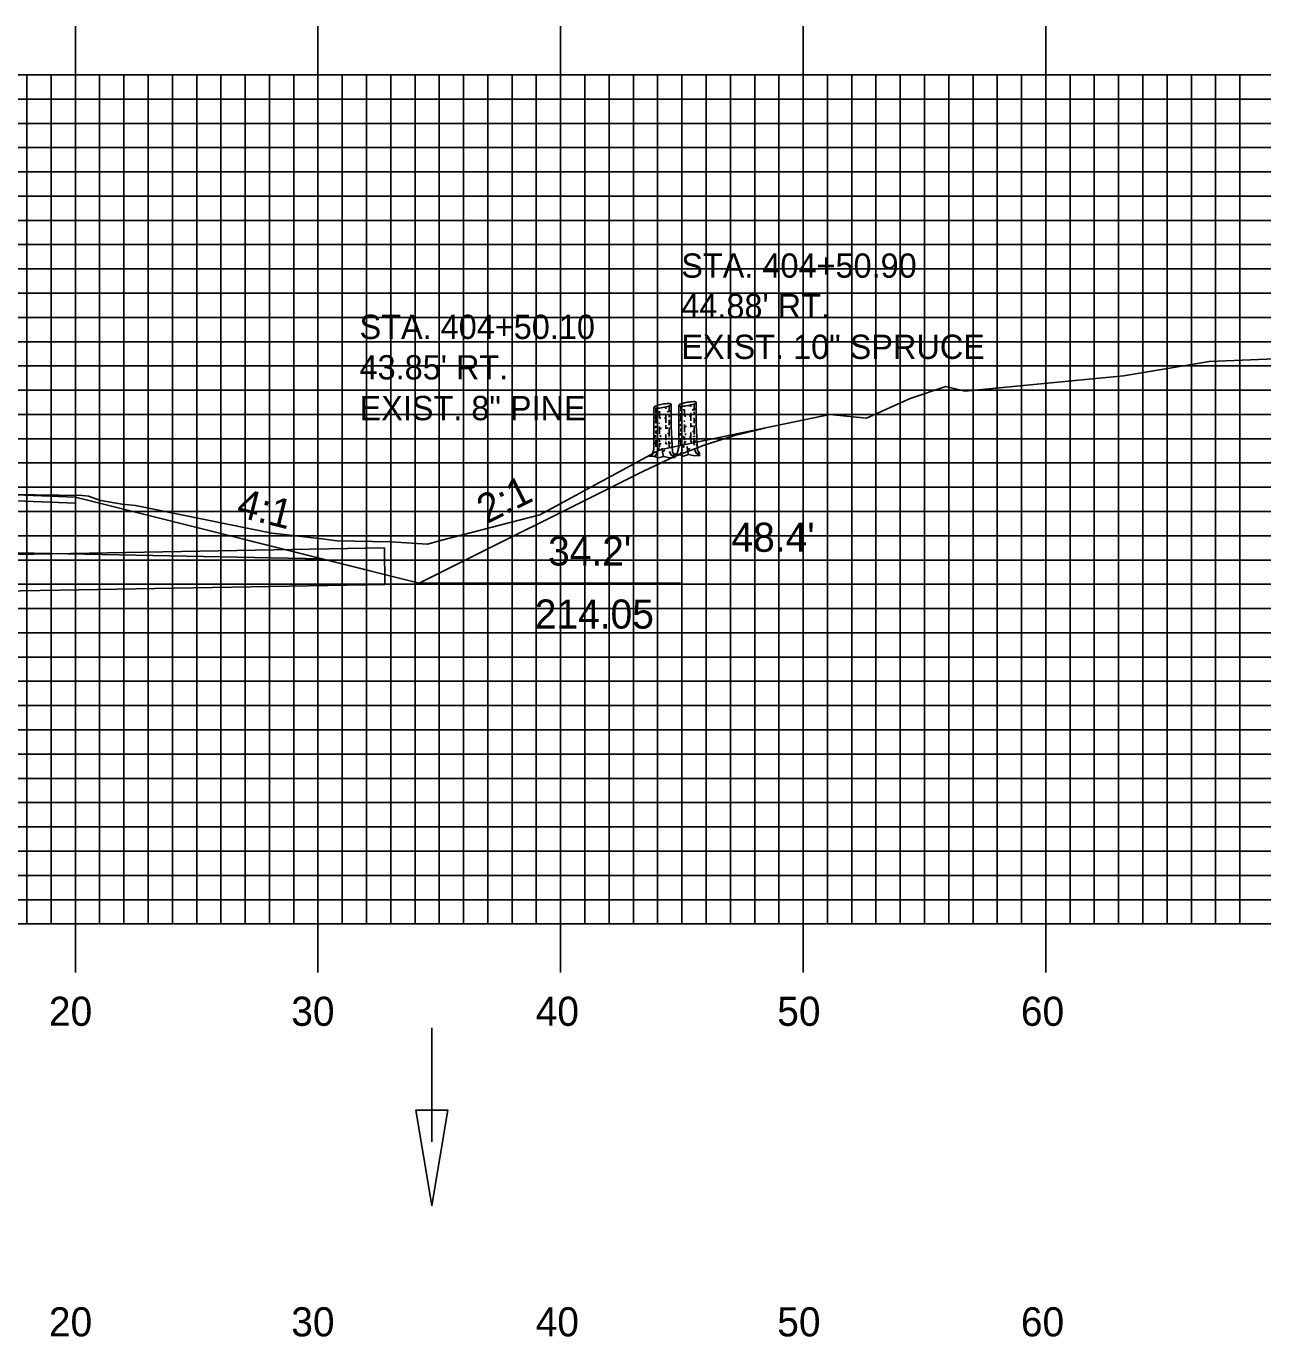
# Model space of a CAD drawing. Extents: x 851348 to 851692, y 364785 to 365005.
# Drawn here: x 851532.2 to 851583.1, y 364841.2 to 364895.2 of the extents above; entities that cross this region are included whole.
import ezdxf

# ---------------------------------------------------------------- set-up
doc = ezdxf.new("R2010")
doc.units = 0
for name, color, linetype in [('ANNOTATION', 7, 'Continuous'), ('D_Drainage_Culvert', 7, 'Continuous'), ('D_Drainage_Ditch_Line', 7, 'Continuous'), ('D_Roadway_Centerline', 7, 'Continuous'), ('D_Roadway_Edge_Shoulder', 7, 'Continuous'), ('D_Roadway_SlopeLines', 7, 'Continuous'), ('D_Roadway_SubGrade', 7, 'Continuous'), ('D_Text_Monospaced', 7, 'Continuous'), ('D_Text_Standard', 7, 'Continuous'), ('H_V ANNOTATION', 7, 'Continuous'), ('MAJOR', 7, 'Continuous'), ('MINOR', 7, 'Continuous'), ('PDRAIN', 7, 'Continuous'), ('S_Roadway_Centerline', 7, 'Continuous'), ('S_Trees_Conifer_NonPay', 7, 'Continuous')]:
    doc.layers.add(name, color=color, linetype=linetype)

msp = doc.modelspace()

# ---------------------------------------------------------------- linework, layer by layer
at = {"layer": 'D_Drainage_Culvert'}
msp.add_line((851472.732, 364872.438), (851546.926, 364873.729), dxfattribs=at)
msp.add_lwpolyline([(851472.732, 364872.438), (851472.758, 364870.938), (851546.952, 364872.229), (851546.926, 364873.729)], dxfattribs=at)
at = {"layer": 'D_Drainage_Ditch_Line'}
msp.add_line((851548.885, 364849.246), (851548.885, 364853.945), dxfattribs=at)
msp.add_lwpolyline([(851548.229, 364850.558), (851549.541, 364850.558), (851548.885, 364846.621)], close=True, dxfattribs=at)
at = {"layer": 'D_Roadway_Centerline'}
msp.add_lwpolyline([(851484.018, 364873.28), (851494.191, 364875.823), (851502.191, 364876.143), (851514.191, 364876.383), (851526.191, 364876.143), (851534.191, 364875.823), (851544.365, 364873.28), (851548.365, 364872.28), (851557.607, 364876.901), (851558.857, 364877.48), (851560.107, 364877.969), (851561.357, 364878.366), (851562.607, 364878.671)], dxfattribs=at)
at = {"layer": 'D_Roadway_Edge_Shoulder'}
msp.add_lwpolyline([(851526.191, 364876.143), (851534.191, 364875.823), (851534.191, 364875.573), (851526.191, 364875.893)], close=True, dxfattribs=at)
at = {"layer": 'D_Roadway_SlopeLines'}
for points in [[(851548.365, 364872.28), (851557.607, 364876.901), (851558.857, 364877.48), (851560.107, 364877.969), (851561.357, 364878.366), (851562.607, 364878.671)], [(851534.191, 364875.823), (851548.365, 364872.28)]]:
    msp.add_lwpolyline(points, dxfattribs=at)
at = {"layer": 'D_Roadway_SubGrade'}
msp.add_lwpolyline([(851502.191, 364873.643), (851484.018, 364873.28), (851494.191, 364875.823), (851494.191, 364875.573), (851502.191, 364875.893), (851514.191, 364876.133), (851526.191, 364875.893), (851534.191, 364875.573), (851534.191, 364875.823), (851544.365, 364873.28), (851526.191, 364873.643), (851514.191, 364873.883)], close=True, dxfattribs=at)
at = {"layer": 'MAJOR'}
for p, q in [((851534.191, 364895.237), (851534.191, 364893.233)), ((851544.191, 364895.237), (851544.191, 364893.233)), ((851554.191, 364895.237), (851554.191, 364893.233)), ((851564.191, 364895.237), (851564.191, 364893.233)), ((851574.191, 364895.237), (851574.191, 364893.233)), ((851374.191, 364893.233), (851654.191, 364893.233)), ((851374.191, 364893.233), (851654.191, 364893.233)), ((851534.191, 364858.233), (851534.191, 364893.233)), ((851544.191, 364858.233), (851544.191, 364893.233)), ((851554.191, 364858.233), (851554.191, 364893.233)), ((851564.191, 364858.233), (851564.191, 364893.233)), ((851574.191, 364858.233), (851574.191, 364893.233)), ((851374.191, 364888.233), (851654.191, 364888.233)), ((851374.191, 364883.233), (851654.191, 364883.233)), ((851374.191, 364878.233), (851654.191, 364878.233)), ((851374.191, 364873.233), (851654.191, 364873.233)), ((851374.191, 364868.233), (851654.191, 364868.233)), ((851374.191, 364863.233), (851654.191, 364863.233)), ((851374.191, 364858.233), (851654.191, 364858.233)), ((851374.191, 364858.233), (851654.191, 364858.233)), ((851534.191, 364856.229), (851534.191, 364858.233)), ((851544.191, 364856.229), (851544.191, 364858.233)), ((851554.191, 364856.229), (851554.191, 364858.233)), ((851564.191, 364856.229), (851564.191, 364858.233)), ((851574.191, 364856.229), (851574.191, 364858.233))]:
    msp.add_line(p, q, dxfattribs=at)
at = {"layer": 'MINOR'}
for p, q in [((851532.191, 364858.233), (851532.191, 364893.233)), ((851533.191, 364858.233), (851533.191, 364893.233)), ((851535.191, 364858.233), (851535.191, 364893.233)), ((851536.191, 364858.233), (851536.191, 364893.233)), ((851537.191, 364858.233), (851537.191, 364893.233)), ((851538.191, 364858.233), (851538.191, 364893.233)), ((851539.191, 364858.233), (851539.191, 364893.233)), ((851540.191, 364858.233), (851540.191, 364893.233)), ((851541.191, 364858.233), (851541.191, 364893.233)), ((851542.191, 364858.233), (851542.191, 364893.233)), ((851543.191, 364858.233), (851543.191, 364893.233)), ((851545.191, 364858.233), (851545.191, 364893.233)), ((851546.191, 364858.233), (851546.191, 364893.233)), ((851547.191, 364858.233), (851547.191, 364893.233)), ((851548.191, 364858.233), (851548.191, 364893.233)), ((851549.191, 364858.233), (851549.191, 364893.233)), ((851550.191, 364858.233), (851550.191, 364893.233)), ((851551.191, 364858.233), (851551.191, 364893.233)), ((851552.191, 364858.233), (851552.191, 364893.233)), ((851553.191, 364858.233), (851553.191, 364893.233)), ((851555.191, 364858.233), (851555.191, 364893.233)), ((851556.191, 364858.233), (851556.191, 364893.233)), ((851557.191, 364858.233), (851557.191, 364893.233)), ((851558.191, 364858.233), (851558.191, 364893.233)), ((851559.191, 364858.233), (851559.191, 364893.233)), ((851560.191, 364858.233), (851560.191, 364893.233)), ((851561.191, 364858.233), (851561.191, 364893.233)), ((851562.191, 364858.233), (851562.191, 364893.233)), ((851563.191, 364858.233), (851563.191, 364893.233)), ((851565.191, 364858.233), (851565.191, 364893.233)), ((851566.191, 364858.233), (851566.191, 364893.233)), ((851567.191, 364858.233), (851567.191, 364893.233)), ((851568.191, 364858.233), (851568.191, 364893.233)), ((851569.191, 364858.233), (851569.191, 364893.233)), ((851570.191, 364858.233), (851570.191, 364893.233)), ((851571.191, 364858.233), (851571.191, 364893.233)), ((851572.191, 364858.233), (851572.191, 364893.233)), ((851573.191, 364858.233), (851573.191, 364893.233)), ((851575.191, 364858.233), (851575.191, 364893.233)), ((851576.191, 364858.233), (851576.191, 364893.233)), ((851577.191, 364858.233), (851577.191, 364893.233)), ((851578.191, 364858.233), (851578.191, 364893.233)), ((851579.191, 364858.233), (851579.191, 364893.233)), ((851580.191, 364858.233), (851580.191, 364893.233)), ((851581.191, 364858.233), (851581.191, 364893.233)), ((851582.191, 364858.233), (851582.191, 364893.233)), ((851374.191, 364892.233), (851654.191, 364892.233)), ((851374.191, 364891.233), (851654.191, 364891.233)), ((851374.191, 364890.233), (851654.191, 364890.233)), ((851374.191, 364889.233), (851654.191, 364889.233)), ((851374.191, 364887.233), (851654.191, 364887.233)), ((851374.191, 364886.233), (851654.191, 364886.233)), ((851374.191, 364885.233), (851654.191, 364885.233)), ((851374.191, 364884.233), (851654.191, 364884.233)), ((851374.191, 364882.233), (851654.191, 364882.233)), ((851374.191, 364881.233), (851654.191, 364881.233)), ((851374.191, 364880.233), (851654.191, 364880.233)), ((851374.191, 364879.233), (851654.191, 364879.233)), ((851374.191, 364877.233), (851654.191, 364877.233)), ((851374.191, 364876.233), (851654.191, 364876.233)), ((851374.191, 364875.233), (851654.191, 364875.233)), ((851374.191, 364874.233), (851654.191, 364874.233)), ((851374.191, 364872.233), (851654.191, 364872.233)), ((851374.191, 364871.233), (851654.191, 364871.233)), ((851374.191, 364870.233), (851654.191, 364870.233)), ((851374.191, 364869.233), (851654.191, 364869.233)), ((851374.191, 364867.233), (851654.191, 364867.233)), ((851374.191, 364866.233), (851654.191, 364866.233)), ((851374.191, 364865.233), (851654.191, 364865.233)), ((851374.191, 364864.233), (851654.191, 364864.233)), ((851374.191, 364862.233), (851654.191, 364862.233)), ((851374.191, 364861.233), (851654.191, 364861.233)), ((851374.191, 364860.233), (851654.191, 364860.233)), ((851374.191, 364859.233), (851654.191, 364859.233))]:
    msp.add_line(p, q, dxfattribs=at)
at = {"layer": 'PDRAIN'}
msp.add_line((851548.365, 364872.28), (851559.136, 364872.28), dxfattribs=at)
at = {"layer": 'S_Roadway_Centerline'}
msp.add_lwpolyline([(851530.584, 364875.954), (851534.474, 364875.898), (851534.731, 364875.863), (851535.225, 364875.692), (851536.116, 364875.529), (851536.67, 364875.476), (851542.288, 364874.334), (851544.359, 364874.112), (851544.968, 364874.02), (851547.184, 364873.987), (851548.701, 364873.888), (851549.301, 364874.056), (851553.335, 364875.102), (851557.74, 364877.491), (851558.095, 364877.681), (851558.341, 364877.783), (851565.291, 364879.23), (851566.803, 364879.082), (851568.595, 364879.89), (851570.066, 364880.38), (851570.855, 364880.187), (851577.397, 364880.822), (851580.934, 364881.423), (851587.352, 364881.676)], dxfattribs=at)
at = {"layer": 'S_Trees_Conifer_NonPay'}
for p, q in [((851558.115, 364879.488), (851558.115, 364879.283)), ((851558.115, 364879.21), (851558.115, 364878.878)), ((851558.272, 364879.363), (851558.272, 364879.09)), ((851558.534, 364879.543), (851558.534, 364879.464)), ((851558.534, 364879.215), (851558.534, 364878.89)), ((851558.669, 364879.254), (851558.669, 364879.124)), ((851559.147, 364879.568), (851559.147, 364879.363)), ((851559.147, 364879.29), (851559.147, 364878.959)), ((851559.304, 364879.444), (851559.304, 364879.17)), ((851559.566, 364879.623), (851559.566, 364879.545)), ((851559.566, 364879.295), (851559.566, 364878.97)), ((851559.7, 364879.335), (851559.7, 364879.204)), ((851558.115, 364878.764), (851558.115, 364878.686)), ((851558.272, 364878.736), (851558.272, 364878.418)), ((851558.534, 364878.789), (851558.534, 364878.635)), ((851558.669, 364879.015), (851558.669, 364878.789)), ((851558.669, 364878.697), (851558.669, 364878.321)), ((851559.147, 364878.844), (851559.147, 364878.766)), ((851559.147, 364878.652), (851559.147, 364878.542)), ((851559.304, 364878.816), (851559.304, 364878.498)), ((851559.566, 364878.869), (851559.566, 364878.715)), ((851559.7, 364879.095), (851559.7, 364878.869)), ((851559.7, 364878.777), (851559.7, 364878.401)), ((851558.098, 364878.384), (851558.098, 364878.287)), ((851558.115, 364878.571), (851558.115, 364878.462)), ((851558.115, 364878.173), (851558.115, 364877.905)), ((851558.272, 364878.248), (851558.272, 364878.088)), ((851558.314, 364878.373), (851558.314, 364878.304)), ((851558.534, 364878.407), (851558.534, 364878.173)), ((851558.534, 364878.111), (851558.534, 364878.025)), ((851558.65, 364878.128), (851558.667, 364877.882)), ((851559.13, 364878.465), (851559.13, 364878.367)), ((851559.147, 364878.253), (851559.147, 364877.986)), ((851559.304, 364878.328), (851559.304, 364878.169)), ((851559.304, 364878.111), (851559.304, 364877.98)), ((851559.345, 364878.453), (851559.345, 364878.384)), ((851559.566, 364878.487), (851559.566, 364878.253)), ((851559.566, 364878.191), (851559.566, 364878.105)), ((851559.682, 364878.208), (851559.699, 364877.963)), ((851558.272, 364878.031), (851558.272, 364877.899)), ((851558.729, 364877.899), (851558.789, 364877.906)), ((851559.76, 364877.98), (851559.821, 364877.986))]:
    msp.add_line(p, q, dxfattribs=at)
for points in [[(851559.811, 364877.619), (851559.927, 364877.628), (851559.835, 364877.753), (851559.802, 364878.294), (851559.781, 364878.811), (851559.781, 364879.73)], [(851558.037, 364879.522), (851558.037, 364877.804), (851557.967, 364877.548), (851557.848, 364877.514), (851558.064, 364877.497), (851558.224, 364877.439), (851558.433, 364877.497), (851558.695, 364877.45), (851558.901, 364877.456), (851558.75, 364877.559), (851558.678, 364877.712)], [(851558.669, 364879.584), (851558.669, 364879.487), (851558.669, 364879.322)], [(851558.779, 364877.539), (851558.896, 364877.548), (851558.804, 364877.673), (851558.77, 364878.214), (851558.75, 364878.731), (851558.75, 364879.65)], [(851559.068, 364879.602), (851559.068, 364877.884), (851558.999, 364877.628), (851558.879, 364877.594), (851559.096, 364877.577), (851559.255, 364877.519), (851559.465, 364877.577), (851559.727, 364877.53), (851559.933, 364877.536), (851559.781, 364877.639), (851559.71, 364877.793)], [(851559.7, 364879.664), (851559.7, 364879.567), (851559.7, 364879.402)], [(851558.064, 364877.497), (851558.154, 364877.609), (851558.171, 364877.724)], [(851558.195, 364877.86), (851558.184, 364877.815), (851558.235, 364877.804), (851558.235, 364877.866)], [(851558.433, 364877.497), (851558.388, 364877.673), (851558.382, 364877.838)], [(851558.386, 364877.723), (851558.456, 364877.718), (851558.474, 364877.77)], [(851559.096, 364877.577), (851559.186, 364877.69), (851559.203, 364877.804)], [(851559.227, 364877.94), (851559.216, 364877.896), (851559.266, 364877.884), (851559.266, 364877.946)], [(851559.465, 364877.577), (851559.42, 364877.753), (851559.414, 364877.918)], [(851559.418, 364877.803), (851559.488, 364877.798), (851559.506, 364877.85)]]:
    msp.add_lwpolyline(points, dxfattribs=at)
for centre, radius, start, end in [((851558.709, 364877.86), 1.825, 92.3651, 100.3798), ((851558.644, 364879.438), 0.245, 70.3798, 92.3651), ((851558.702, 364879.601), 0.0729, 59.1402, 70.3798), ((851559.242, 364879.439), 0.245, 108.3946, 130.3798), ((851559.741, 364877.94), 1.825, 100.3798, 108.3946), ((851559.741, 364877.94), 1.825, 92.3651, 100.3798), ((851559.676, 364879.519), 0.245, 70.3798, 92.3651), ((851559.607, 364879.891), 0.245, 288.3946, 310.3798), ((851559.733, 364879.681), 0.0729, 59.1402, 70.3798), ((851559.719, 364879.76), 0.0729, 310.3798, 321.6195), ((851559.757, 364879.721), 0.0263, 40.3798, 59.1402), ((851559.755, 364879.731), 0.0263, 321.6195, 340.3798), ((851559.763, 364879.726), 0.0186, 26.433, 40.3798), ((851559.767, 364879.728), 0.0141, 10.3798, 26.433), ((851559.763, 364879.728), 0.0186, 340.3798, 354.3267), ((851559.767, 364879.728), 0.0141, 354.3267, 10.3798), ((851558.055, 364879.522), 0.0186, 160.3798, 174.3267), ((851558.051, 364879.522), 0.0141, 174.3267, 190.3798), ((851558.051, 364879.522), 0.0141, 190.3798, 206.433), ((851558.051, 364879.407), 0.0143, 180, 196.0515), ((851558.062, 364879.519), 0.0263, 141.6195, 160.3798), ((851558.055, 364879.524), 0.0186, 206.433, 220.3798), ((851558.061, 364879.529), 0.0263, 220.3798, 239.1402), ((851558.099, 364879.49), 0.0729, 130.3798, 141.6195), ((851558.084, 364879.569), 0.0729, 239.1402, 250.3798), ((851558.211, 364879.359), 0.245, 108.3946, 130.3798), ((851558.142, 364879.732), 0.245, 250.3798, 272.3651), ((851558.179, 364879.595), 0.245, 254.8461, 261.8968), ((851558.709, 364877.86), 1.825, 100.3798, 108.3946), ((851558.394, 364881.103), 1.767, 261.8968, 262.605), ((851558.077, 364881.31), 1.825, 272.3651, 280.3798), ((851558.394, 364881.103), 1.767, 264.3267, 266.0499), ((851558.077, 364881.31), 1.825, 280.3798, 288.3946), ((851558.394, 364881.103), 1.767, 276.2449, 278.1032), ((851558.608, 364879.595), 0.245, 278.1032, 284.1859), ((851558.576, 364879.811), 0.245, 288.3946, 310.3798), ((851558.608, 364879.595), 0.245, 291.7653, 300), ((851558.694, 364879.447), 0.0738, 300, 311.2506), ((851558.687, 364879.68), 0.0729, 310.3798, 321.6195), ((851558.726, 364879.641), 0.0263, 40.3798, 59.1402), ((851558.725, 364879.412), 0.0267, 311.2506, 330), ((851558.727, 364879.159), 0.0267, 311.2506, 330), ((851558.724, 364879.651), 0.0263, 321.6195, 340.3798), ((851558.732, 364879.646), 0.0186, 26.433, 40.3798), ((851558.736, 364879.648), 0.0141, 10.3798, 26.433), ((851558.732, 364879.408), 0.0189, 330, 343.9485), ((851558.736, 364879.648), 0.0141, 354.3267, 10.3798), ((851558.731, 364879.648), 0.0186, 340.3798, 354.3267), ((851558.733, 364879.156), 0.0189, 330, 343.9485), ((851559.087, 364879.602), 0.0186, 160.3798, 174.3267), ((851559.082, 364879.602), 0.0141, 174.3267, 190.3798), ((851559.082, 364879.602), 0.0141, 190.3798, 206.433), ((851559.094, 364879.599), 0.0263, 141.6195, 160.3798), ((851559.083, 364879.487), 0.0143, 180, 196.0515), ((851559.086, 364879.604), 0.0186, 206.433, 220.3798), ((851559.092, 364879.609), 0.0263, 220.3798, 239.1402), ((851559.131, 364879.571), 0.0729, 130.3798, 141.6195), ((851559.116, 364879.649), 0.0729, 239.1402, 250.3798), ((851559.174, 364879.812), 0.245, 250.3798, 272.3651), ((851559.212, 364879.423), 0.245, 244.3148, 257.5375), ((851559.211, 364879.675), 0.245, 254.8461, 261.8968), ((851559.425, 364881.183), 1.767, 261.8968, 262.605), ((851559.109, 364881.391), 1.825, 272.3651, 280.3798), ((851559.425, 364881.183), 1.767, 264.3267, 266.0499), ((851559.427, 364880.93), 1.767, 265.8991, 267.5962), ((851559.109, 364881.391), 1.825, 280.3798, 288.3946), ((851559.427, 364880.93), 1.767, 272.7221, 274.4847), ((851559.425, 364881.183), 1.767, 276.2449, 278.1032), ((851559.64, 364879.675), 0.245, 278.1032, 284.1859), ((851559.64, 364879.675), 0.245, 291.7653, 300), ((851559.725, 364879.527), 0.0738, 300, 311.2506), ((851559.756, 364879.492), 0.0267, 311.2506, 330), ((851559.758, 364879.24), 0.0267, 311.2506, 330), ((851559.763, 364879.488), 0.0189, 330, 343.9485), ((851559.765, 364879.236), 0.0189, 330, 343.9485), ((851558.051, 364878.94), 0.0143, 180, 196.0515), ((851558.052, 364878.729), 0.0143, 180, 196.0515), ((851558.056, 364878.942), 0.0189, 196.0515, 210), ((851558.056, 364878.73), 0.0189, 196.0515, 210), ((851558.063, 364878.946), 0.0267, 210, 228.7494), ((851558.063, 364878.734), 0.0267, 210, 228.7494), ((851558.094, 364878.981), 0.0738, 228.7494, 240), ((851558.094, 364878.77), 0.0738, 228.7494, 240), ((851558.179, 364879.129), 0.245, 240, 246.7914), ((851558.179, 364878.918), 0.245, 240, 254.9514), ((851558.181, 364879.343), 0.245, 244.3148, 257.5375), ((851558.179, 364879.129), 0.245, 254.8461, 257.5454), ((851558.394, 364880.636), 1.767, 265.2285, 266.1325), ((851558.396, 364880.85), 1.767, 265.8991, 267.5962), ((851558.394, 364880.425), 1.767, 266.0429, 268.5525), ((851558.396, 364880.85), 1.767, 272.7221, 274.4847), ((851558.394, 364880.425), 1.767, 274.5361, 277.0026), ((851558.608, 364879.129), 0.245, 284.1859, 300), ((851558.609, 364878.918), 0.245, 292.1924, 300), ((851558.694, 364878.981), 0.0738, 300, 311.2506), ((851558.694, 364878.77), 0.0738, 300, 311.2506), ((851558.725, 364878.946), 0.0267, 311.2506, 330), ((851558.725, 364878.734), 0.0267, 311.2506, 330), ((851558.732, 364878.942), 0.0189, 330, 343.9485), ((851558.732, 364878.73), 0.0189, 330, 343.9485), ((851559.083, 364879.021), 0.0143, 180, 196.0515), ((851559.087, 364879.022), 0.0189, 196.0515, 210), ((851559.083, 364878.809), 0.0143, 180, 196.0515), ((851559.088, 364878.811), 0.0189, 196.0515, 210), ((851559.094, 364879.026), 0.0267, 210, 228.7494), ((851559.094, 364878.814), 0.0267, 210, 228.7494), ((851559.125, 364879.061), 0.0738, 228.7494, 240), ((851559.125, 364878.85), 0.0738, 228.7494, 240), ((851559.211, 364879.209), 0.245, 240, 246.7914), ((851559.211, 364878.998), 0.245, 240, 254.9514), ((851559.211, 364879.209), 0.245, 254.8461, 257.5454), ((851559.425, 364880.717), 1.767, 265.2285, 266.1325), ((851559.426, 364880.505), 1.767, 266.0429, 268.5525), ((851559.426, 364880.505), 1.767, 274.5361, 277.0026), ((851559.64, 364879.209), 0.245, 284.1859, 300), ((851559.64, 364878.998), 0.245, 292.1924, 300), ((851559.725, 364879.061), 0.0738, 300, 311.2506), ((851559.726, 364878.85), 0.0738, 300, 311.2506), ((851559.756, 364879.026), 0.0267, 311.2506, 330), ((851559.757, 364878.814), 0.0267, 311.2506, 330), ((851559.763, 364879.022), 0.0189, 330, 343.9485), ((851559.763, 364878.811), 0.0189, 330, 343.9485), ((851558.05, 364878.087), 0.0143, 180, 196.0515), ((851558.051, 364878.293), 0.0143, 180, 196.0515), ((851558.055, 364878.088), 0.0189, 196.0515, 210), ((851558.062, 364878.092), 0.0267, 210, 228.7494), ((851558.093, 364878.127), 0.0738, 228.7494, 240), ((851558.178, 364878.275), 0.245, 240, 249.1675), ((851558.179, 364878.698), 0.245, 254.9814, 261.8968), ((851558.393, 364880.206), 1.767, 261.8968, 262.45), ((851558.393, 364879.989), 1.767, 262.2622, 265.0496), ((851558.393, 364879.989), 1.767, 272.6293, 274.5612), ((851558.393, 364880.206), 1.767, 276.7966, 278.1032), ((851558.393, 364879.989), 1.767, 277.63, 278.1032), ((851558.608, 364878.698), 0.245, 278.1032, 284.3207), ((851558.608, 364878.481), 0.245, 278.1032, 294.6056), ((851558.607, 364878.275), 0.245, 284.0684, 300), ((851558.693, 364878.127), 0.0738, 300, 302.05), ((851559.082, 364878.373), 0.0143, 180, 196.0515), ((851559.082, 364878.167), 0.0143, 180, 196.0515), ((851559.086, 364878.168), 0.0189, 196.0515, 210), ((851559.093, 364878.172), 0.0267, 210, 228.7494), ((851559.124, 364878.208), 0.0738, 228.7494, 240), ((851559.21, 364878.356), 0.245, 240, 249.1675), ((851559.21, 364878.778), 0.245, 254.9814, 261.8968), ((851559.425, 364880.286), 1.767, 261.8968, 262.45), ((851559.425, 364880.069), 1.767, 262.2622, 265.0496), ((851559.424, 364879.863), 1.767, 266.0862, 268.2187), ((851559.425, 364880.069), 1.767, 272.6293, 274.5612), ((851559.424, 364879.863), 1.767, 274.2776, 276.3006), ((851559.425, 364880.286), 1.767, 276.7966, 278.1032), ((851559.425, 364880.069), 1.767, 277.63, 278.1032), ((851559.639, 364878.778), 0.245, 278.1032, 284.3207), ((851559.639, 364878.561), 0.245, 278.1032, 294.6056), ((851559.639, 364878.356), 0.245, 284.0684, 300), ((851559.724, 364878.208), 0.0738, 300, 302.05), ((851558.393, 364879.783), 1.767, 266.0862, 268.2187), ((851558.393, 364879.783), 1.767, 274.2776, 276.3006)]:
    msp.add_arc(centre, radius, start, end, dxfattribs=at)

# ---------------------------------------------------------------- texts
at = {"layer": 'ANNOTATION'}
for s, rotation, p in [('2:1', 26.5651, (851551.132, 364874.699)), ('4:1', 345.9638, (851540.784, 364875.037))]:
    msp.add_text(s, height=1.2, rotation=rotation, dxfattribs=at).set_placement(p)
for s, p in [("34.2'", (851553.675, 364873.006)), ('214.05', (851553.129, 364870.406))]:
    msp.add_text(s, height=1.2, dxfattribs=at).set_placement(p)
at = {"layer": 'D_Text_Monospaced'}
for s, height, p in [('STA. 404+50.90', 0.99996, (851559.167, 364884.87)), ("44.88' RT.", 1, (851559.167, 364883.202)), ('STA. 404+50.10', 0.99996, (851545.905, 364882.345)), ('EXIST. 10" SPRUCE', 0.99996, (851559.167, 364881.522)), ("43.85' RT.", 1, (851545.905, 364880.677)), ('EXIST. 8" PINE', 0.99996, (851545.905, 364878.997))]:
    msp.add_text(s, height=height, dxfattribs=at).set_placement(p)
at = {"layer": 'D_Text_Standard'}
msp.add_text("48.4'", height=1.2, dxfattribs=at).set_placement((851561.236, 364873.572))
at = {"layer": 'H_V ANNOTATION'}
for s, p in [('20', (851533.099, 364854.033)), ('30', (851543.089, 364854.033)), ('40', (851553.164, 364854.033)), ('50', (851563.121, 364854.033)), ('60', (851573.164, 364854.033)), ('20', (851533.099, 364841.233)), ('30', (851543.089, 364841.233)), ('40', (851553.164, 364841.233)), ('50', (851563.121, 364841.233)), ('60', (851573.164, 364841.233))]:
    msp.add_text(s, height=1.2, dxfattribs=at).set_placement(p)

doc.saveas('drawing.dxf')
